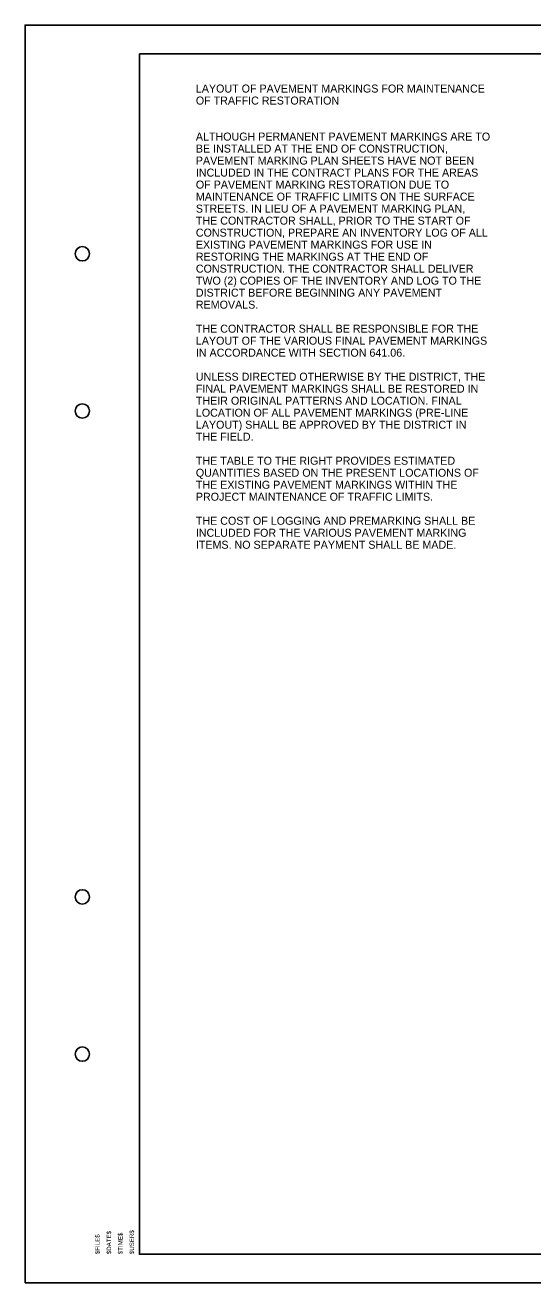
# Model space of a CAD drawing. Extents: x 1822205 to 1824724, y 710141 to 711863.
# Drawn here: x 1822341 to 1822785, y 710141 to 711241 of the extents above; entities that cross this region are included whole.
import ezdxf

# ---------------------------------------------------------------- set-up
doc = ezdxf.new("R2010")
doc.units = 0
for name, color, linetype in [('SH_Border', 7, 'Continuous'), ('SH_Cut_Line', 7, 'Continuous'), ('SH_Text', 7, 'Continuous'), ('TX_P_Misc', 7, 'Continuous')]:
    doc.layers.add(name, color=color, linetype=linetype)

msp = doc.modelspace()

# ---------------------------------------------------------------- linework, layer by layer
at = {"layer": 'SH_Border'}
msp.add_lwpolyline([(1822441.4, 711216.5), (1824016.4, 711216.5), (1824016.4, 710166.5), (1822441.4, 710166.5)], close=True, dxfattribs=at)
for centre in [(1822391.4, 711041.5), (1822391.4, 710904), (1822391.4, 710479), (1822391.4, 710341.5)]:
    msp.add_circle(centre, 6.25, dxfattribs=at)
at = {"layer": 'SH_Cut_Line'}
msp.add_lwpolyline([(1822341.4, 710141.5), (1824041.4, 710141.5), (1824041.4, 711241.5), (1822341.4, 711241.5)], close=True, dxfattribs=at)

# ---------------------------------------------------------------- texts
at = {"layer": 'SH_Text'}
for s, p in [('LAYOUT OF PAVEMENT MARKINGS FOR MAINTENANCE ', (1822490.7, 711182.5)), ('OF TRAFFIC RESTORATION', (1822490.7, 711172)), ('ALTHOUGH PERMANENT PAVEMENT MARKINGS ARE TO ', (1822490.7, 711140.5)), ('BE INSTALLED AT THE END OF CONSTRUCTION, ', (1822490.7, 711130)), ('PAVEMENT MARKING PLAN SHEETS HAVE NOT BEEN ', (1822490.7, 711119.5)), ('INCLUDED IN THE CONTRACT PLANS FOR THE AREAS ', (1822490.7, 711109)), ('OF PAVEMENT MARKING RESTORATION DUE TO ', (1822490.7, 711098.5)), ('MAINTENANCE OF TRAFFIC LIMITS ON THE SURFACE ', (1822490.7, 711088)), ('STREETS. IN LIEU OF A PAVEMENT MARKING PLAN, ', (1822490.7, 711077.5)), ('THE CONTRACTOR SHALL, PRIOR TO THE START OF ', (1822490.7, 711067)), ('CONSTRUCTION, PREPARE AN INVENTORY LOG OF ALL ', (1822490.7, 711056.5)), ('EXISTING PAVEMENT MARKINGS FOR USE IN ', (1822490.7, 711046)), ('RESTORING THE MARKINGS AT THE END OF ', (1822490.7, 711035.5)), ('CONSTRUCTION. THE CONTRACTOR SHALL DELIVER ', (1822490.7, 711025)), ('TWO (2) COPIES OF THE INVENTORY AND LOG TO THE ', (1822490.7, 711014.5)), ('DISTRICT BEFORE BEGINNING ANY PAVEMENT ', (1822490.7, 711004)), ('REMOVALS. ', (1822490.7, 710993.5)), ('THE CONTRACTOR SHALL BE RESPONSIBLE FOR THE ', (1822490.7, 710972.5)), ('LAYOUT OF THE VARIOUS FINAL PAVEMENT MARKINGS ', (1822490.7, 710962)), ('IN ACCORDANCE WITH SECTION 641.06.', (1822490.7, 710951.5)), ('UNLESS DIRECTED OTHERWISE BY THE DISTRICT, THE ', (1822490.7, 710930.5)), ('FINAL PAVEMENT MARKINGS SHALL BE RESTORED IN ', (1822490.7, 710920)), ('THEIR ORIGINAL PATTERNS AND LOCATION. FINAL ', (1822490.7, 710909.5)), ('LOCATION OF ALL PAVEMENT MARKINGS (PRE-LINE ', (1822490.7, 710899)), ('LAYOUT) SHALL BE APPROVED BY THE DISTRICT IN ', (1822490.7, 710888.5)), ('THE FIELD.', (1822490.7, 710878)), ('THE TABLE TO THE RIGHT PROVIDES ESTIMATED ', (1822490.7, 710857)), ('QUANTITIES BASED ON THE PRESENT LOCATIONS OF ', (1822490.7, 710846.5)), ('THE EXISTING PAVEMENT MARKINGS WITHIN THE ', (1822490.7, 710836)), ('PROJECT MAINTENANCE OF TRAFFIC LIMITS. ', (1822490.7, 710825.5)), ('THE COST OF LOGGING AND PREMARKING SHALL BE ', (1822490.7, 710804.5)), ('INCLUDED FOR THE VARIOUS PAVEMENT MARKING ', (1822490.7, 710794)), ('ITEMS. NO SEPARATE PAYMENT SHALL BE MADE. ', (1822490.7, 710783.5))]:
    msp.add_text(s, height=7, rotation=360, dxfattribs=at).set_placement(p)
at = {"layer": 'TX_P_Misc'}
for s, p in [('$FILE$', (1822406.6, 710166.5)), ('$DATE$', (1822416.6, 710166.5)), ('$TIME$', (1822426.6, 710166.5)), ('$USER$', (1822436.6, 710166.5))]:
    msp.add_text(s, height=3.9, rotation=90, dxfattribs=at).set_placement(p)

doc.saveas('drawing.dxf')
